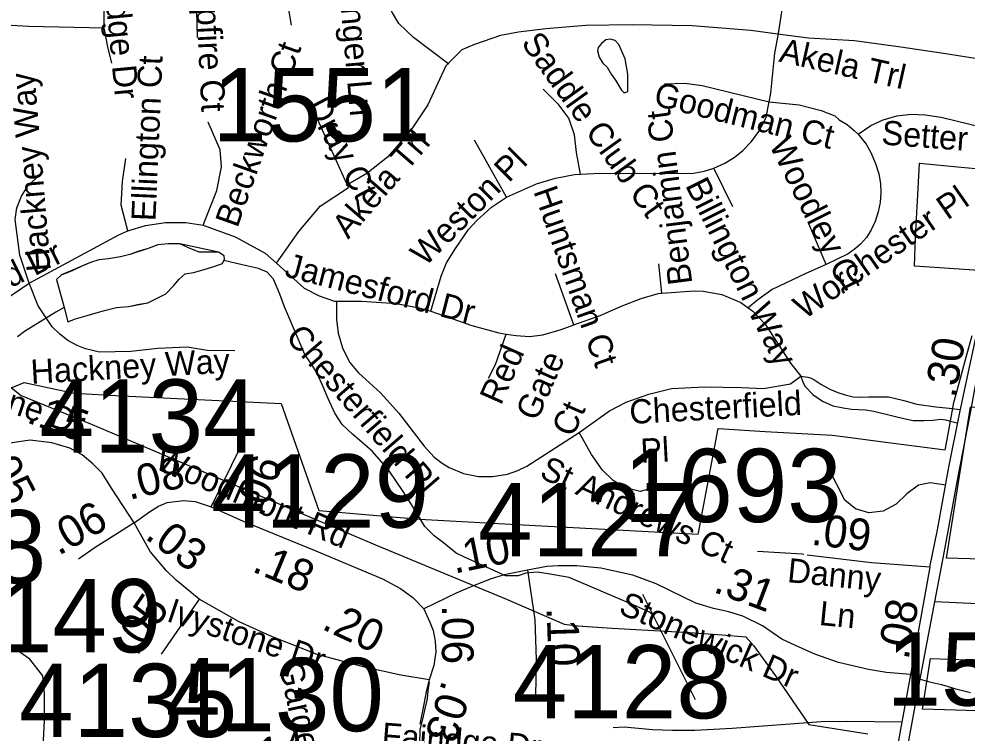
# Model space of a CAD drawing. Extents: x 1662474 to 1856135, y 779280 to 917889.
# Drawn here: x 1723616 to 1727342, y 830593 to 833399 of the extents above; entities that cross this region are included whole.
import ezdxf

# ---------------------------------------------------------------- set-up
doc = ezdxf.new("R2010")
doc.units = 0
for name, color, linetype in [('Cogo Default Point CELL', 7, 'Continuous'), ('Exist Boundary Political City Limit New', 7, 'Continuous'), ('Exist Hydrographic Misc Water Feature', 7, 'Continuous'), ('Exist Hydrographic Pond Under 1500 Sq Ft', 7, 'Continuous'), ('Exist Road Non-System Type 51', 7, 'Continuous'), ('Exist Road Non-System Type 51 Label', 7, 'Continuous'), ('Exist Road Secondary Mileage Tenths English Label', 7, 'Continuous'), ('Exist Road Secondary Type 51 Attributed', 7, 'Continuous'), ('Exist Road Secondary Type 51 Divided Attributed', 7, 'Continuous'), ('Exist Road Secondary Type 51 Label', 7, 'Continuous'), ('Exist Utilities Electrical Transmission Line', 7, 'Continuous'), ('Map Preparation Boundary City Limit Buffer Line', 7, 'Continuous')]:
    doc.layers.add(name, color=color, linetype=linetype)

msp = doc.modelspace()

# ---------------------------------------------------------------- linework, layer by layer
at = {"layer": 'Exist Boundary Political City Limit New'}
for points in [[(1727389.6, 832410), (1727135.1, 832427.2), (1727140.2, 832541.9), (1727148.4, 832707), (1727154.9, 832832.4), (1727156.5, 832832.2), (1727276.9, 832820.2), (1727431.2, 832805.6)], [(1725190.4, 831433.2), (1725573.1, 831412.8), (1726285.4, 831373.6), (1726286.4, 831378.9), (1726364.4, 831789), (1726365.4, 831788.9), (1726549.1, 831778.2), (1726812.6, 831763.2), (1726854.1, 831757.9), (1727012.6, 831737.3), (1727256.6, 831705.6), (1727257.6, 831711.1), (1727269.5, 831775.4), (1727290.5, 831891), (1727299.9, 831924.6), (1727339.2, 832069.2), (1727362.8, 832154.9)], [(1723288, 831825.6), (1723636.5, 831970.3), (1723833.2, 831927.6), (1724020.8, 831917.3), (1724646, 831887.5), (1724794.4, 831467.4), (1724795.4, 831467.4), (1724870, 831460.9), (1725190.4, 831433.2)], [(1729142.6, 831829.8), (1729118.1, 831226.9), (1727260.9, 831280.2), (1727355.8, 831874.2), (1729142.6, 831829.8)], [(1729103.2, 830822.3), (1729099, 830629.8), (1728968.8, 830633.4), (1728118.2, 830657.7), (1727167, 830686.4), (1727177.1, 830753.4), (1727199.1, 830885.4), (1727347.4, 830880.3), (1727479.9, 830875.7), (1727771.5, 830865.6), (1728174.1, 830851.8), (1728462.2, 830842.8), (1728946.4, 830827.4), (1729103.2, 830822.3)]]:
    msp.add_lwpolyline(points, dxfattribs=at)
at = {"layer": 'Exist Hydrographic Misc Water Feature'}
for points in [[(1724421.6, 832449.4), (1724424, 832454.3), (1724422, 832468.3), (1724400.1, 832481.9), (1724366.2, 832482.5), (1724324.2, 832482.5), (1724282.1, 832499.1), (1724248.1, 832514.5), (1724202.2, 832514.6), (1724162, 832511.3), (1724124.1, 832497.3), (1724087.8, 832485.7), (1724051.7, 832473.4), (1724015.6, 832463.4), (1723967.4, 832456.2), (1723929.7, 832452), (1723897.5, 832442), (1723865.3, 832428), (1723827.3, 832410.6), (1723799, 832398.1), (1723783.1, 832392.7), (1723763.6, 832375), (1723793.5, 832264.4)], [(1724421.6, 832449.4), (1724424, 832454.3), (1724422, 832468.3), (1724400.1, 832481.9), (1724248.1, 832514.5), (1724202.2, 832514.6), (1724162, 832511.3), (1724124.1, 832497.3), (1724051.7, 832473.4), (1724015.6, 832463.4), (1723967.4, 832456.2), (1723929.7, 832452), (1723897.5, 832442), (1723783.1, 832392.7), (1723763.6, 832375), (1723793.5, 832264.4)], [(1723793.5, 832264.4), (1723808.5, 832208.3), (1723838.2, 832220), (1723884.6, 832233.9), (1723946.7, 832251.5), (1723999, 832265.2), (1724047, 832269.1), (1724089, 832277.3), (1724123.2, 832283.2), (1724159.1, 832301.3), (1724193.2, 832318.7), (1724225.3, 832350.9), (1724245.4, 832376.7), (1724269.6, 832396.7), (1724301.8, 832402.6), (1724343.9, 832414.1), (1724381.8, 832426.4), (1724415.8, 832438), (1724421.6, 832449.4)], [(1723793.5, 832264.4), (1723808.5, 832208.3), (1723838.2, 832220), (1723884.6, 832233.9), (1723946.7, 832251.5), (1723999, 832265.2), (1724047, 832269.1), (1724123.2, 832283.2), (1724159.1, 832301.3), (1724193.2, 832318.7), (1724225.3, 832350.9), (1724245.4, 832376.7), (1724269.6, 832396.7), (1724301.8, 832402.6), (1724343.9, 832414.1), (1724381.8, 832426.4), (1724415.8, 832438), (1724421.6, 832449.4)], [(1725126.1, 831542.3), (1725071.2, 831623), (1725041.5, 831658.9), (1725005.4, 831699), (1724963.7, 831735.1), (1724927.7, 831765.4), (1724885.8, 831805.7), (1724857.9, 831849.7), (1724830.3, 831910.1), (1724808.3, 831962.3), (1724786.6, 832008.7), (1724770.6, 832034.5), (1724739, 832080.2), (1724659.4, 832267.3), (1724641.8, 832316.9), (1724616.2, 832375.7), (1724592, 832403.3), (1724558.1, 832417.9), (1724510, 832428), (1724421.6, 832449.4)], [(1723793.5, 832264.4), (1723760.5, 832246.2), (1723638.1, 832170.8), (1723610, 832149.2)], [(1726112, 831052.8), (1726092.1, 831068.8), (1726030.2, 831097.2), (1725778.2, 831204), (1725696.4, 831218), (1725652.3, 831224.7), (1725608, 831220.6), (1725577.9, 831210.6), (1725528, 831210.8), (1725364.2, 831285.5), (1725334.3, 831300), (1725284.2, 831339.6), (1725248.4, 831368.3), (1725210.6, 831404.3), (1725182.7, 831452.5), (1725156.7, 831494.9), (1725126.1, 831542.3)]]:
    msp.add_lwpolyline(points, dxfattribs=at)
at = {"layer": 'Exist Hydrographic Pond Under 1500 Sq Ft'}
msp.add_lwpolyline([(1726008.5, 833115.2), (1726008.5, 833182.1), (1725998.2, 833242.2), (1725974.2, 833298.8), (1725958.7, 833314.3), (1725939.8, 833319.4), (1725922.7, 833316), (1725905.5, 833302.3), (1725891.8, 833286.8), (1725890, 833273.1), (1725896.9, 833249.1), (1725910.7, 833225), (1725927.8, 833209.6), (1725943.3, 833182.1), (1725960.4, 833158.1), (1725975.9, 833132.4), (1725984.5, 833118.6), (1725994.8, 833108.3), (1726006.8, 833111.8), (1726008.5, 833115.2)], dxfattribs=at)
at = {"layer": 'Exist Road Non-System Type 51'}
for p, q in [((1724317.9, 833325.6), (1724308.6, 833723.8)), ((1724911, 832735.9), (1724783.2, 833019.5)), ((1725532, 832698.5), (1725406, 832921.9)), ((1726421.2, 832660.2), (1726347, 832812.2)), ((1726788.4, 832433.2), (1726720.4, 832593.6)), ((1726143, 832321.1), (1726131, 832436.4)), ((1725796.6, 832196.4), (1725724.9, 832397))]:
    msp.add_line(p, q, dxfattribs=at)
for points in [[(1724686.6, 833373.6), (1724662.2, 833523.4), (1724658.9, 833585.9), (1724667.4, 833756.2)], [(1725305.2, 833220.6), (1725166.6, 833325.6), (1725109.5, 833380.7), (1725084, 833422.7), (1725054.2, 833482.2), (1725034.4, 833525.6), (1725017.6, 833599.9), (1725012.6, 833666.5), (1725016.6, 833724.5)], [(1723951.2, 833363.9), (1723951.2, 833406.9), (1723953.4, 833525.6), (1723960.6, 833682)], [(1726599.4, 833333.7), (1726623.6, 833487.2), (1726635.4, 833529.8)], [(1723540.8, 833377), (1723654, 833370.7), (1723951.2, 833363.9)], [(1723981.4, 833224.8), (1723965.9, 833289.4), (1723951.2, 833363.9)], [(1726564.6, 833073.4), (1726571.6, 833107.4), (1726587.1, 833263.9), (1726599.4, 833333.7)], [(1726153, 833143.4), (1726233.6, 833146), (1726301.4, 833137.1), (1726564.6, 833073.4)], [(1725823.1, 832788.9), (1725807.4, 832873.6), (1725798.9, 832943.7), (1725776.9, 833009), (1725737.9, 833061), (1725676.1, 833122.9)], [(1726347, 832812.2), (1726390, 832831.6), (1726426.8, 832854.2), (1726460.4, 832881.2), (1726494.8, 832916.9), (1726523.9, 832956.5), (1726547, 833000.4), (1726552.5, 833013.2), (1726564.6, 833073.4)], [(1726564.6, 833073.4), (1726682.4, 833061), (1726768.8, 833039.2), (1726822.9, 833017.4), (1726839.9, 833002.8), (1726870.6, 832983.6), (1726898.8, 832960.7), (1726914.6, 832945.8)], [(1726914.6, 832945.8), (1726964.5, 832980.1), (1727012.6, 833001.9), (1727065.6, 833017.4), (1727122.6, 833024.5), (1727178.1, 833021.4), (1727240.6, 833012.2), (1727406.2, 832971.8)], [(1724339.9, 832588.4), (1724394, 832725.2), (1724412.4, 832818.2), (1724407.4, 832884.9), (1724359.4, 832993.4)], [(1726914.6, 832945.8), (1726945.4, 832906.2), (1726963.5, 832874.1), (1726982.6, 832830.9), (1726995, 832789.4), (1727001.6, 832752.4), (1727003, 832714.9), (1727000.2, 832677.2), (1726992.6, 832640.5), (1726981.1, 832602.2), (1726965.9, 832570.2), (1726946.6, 832540.5), (1726923.4, 832513.8), (1726903.6, 832496.2), (1726874.8, 832476), (1726788.4, 832433.2)], [(1724043.9, 832566), (1724017.4, 832667), (1724022.4, 832760.2), (1724036, 832850.2)], [(1723655.9, 832359.9), (1723618.9, 832470.4), (1723600.6, 832610.4), (1723607.6, 832657.1), (1723626, 832701.9), (1723652.5, 832743.7), (1723711.6, 832797.8)], [(1725823.1, 832788.9), (1725875.4, 832791.4), (1726266.9, 832792.5), (1726309.4, 832800.1), (1726347, 832812.2)], [(1725532, 832698.5), (1725649.6, 832750.2), (1725724.6, 832773.4), (1725800, 832787.5), (1725823.1, 832788.9)], [(1724627.9, 832438.7), (1724715.5, 832563.7), (1724800.2, 832662.6), (1724911, 832735.9)], [(1725235.1, 832250), (1725275.9, 832388.6), (1725296.1, 832440.9), (1725331.2, 832496.2), (1725382.9, 832571.2), (1725415.8, 832606.4), (1725472.6, 832659.2), (1725532, 832698.5)], [(1724043.9, 832566), (1724113.4, 832587.5), (1724192.4, 832599.4), (1724272.5, 832599.4), (1724339.9, 832588.4)], [(1724339.9, 832588.4), (1724465.6, 832542.4), (1724584, 832478.9), (1724627.9, 832438.7)], [(1723655.9, 832359.9), (1724008.6, 832550.5), (1724043.9, 832566)], [(1724627.9, 832438.7), (1724737.2, 832340.5), (1724795.9, 832311.2), (1724855.6, 832289.9), (1724863.5, 832289.9)], [(1726788.4, 832433.2), (1726708.4, 832398.2), (1726575.9, 832335), (1726519.4, 832295.4), (1726482.4, 832263.4)], [(1723557.8, 832293.9), (1723655.9, 832359.9)], [(1724464.4, 832094.1), (1724355.9, 832095.4), (1724277.1, 832109), (1724162.2, 832103.9), (1724055.8, 832092.5), (1723932.4, 832088.9), (1723877.1, 832101.9), (1723844.4, 832115.4), (1723808.4, 832134.8), (1723776.1, 832160), (1723747.2, 832189.1), (1723691.1, 832272), (1723655.9, 832359.9)], [(1725796.6, 832196.4), (1725900.2, 832233.8), (1725986.6, 832272), (1726060.9, 832299.9), (1726128.4, 832319.9), (1726143, 832321.1)], [(1726143, 832321.1), (1726269.2, 832330.6), (1726304.8, 832328.8), (1726378.1, 832315.4), (1726453.5, 832284.9), (1726482.4, 832263.4)], [(1724863.5, 832289.9), (1724963.2, 832290.2), (1725098.1, 832281.2), (1725188.5, 832263.9), (1725235.1, 832250)], [(1724863.5, 832289.9), (1724863.5, 832217.7), (1724870.9, 832163.4), (1724887.1, 832106.4), (1724915.2, 832049.8), (1724950.4, 832008.5), (1725037.6, 831930.1), (1725108.4, 831849.2), (1725208.1, 831720.1), (1725248.4, 831676.2), (1725279, 831652.9), (1725307.1, 831635.9), (1725362.8, 831612.8), (1725421.8, 831600.9), (1725476.6, 831600.2), (1725535.6, 831610.1), (1725577.1, 831624.2), (1725611.6, 831641.4), (1725817.9, 831773.4)], [(1725235.1, 832250), (1725395.6, 832194.4), (1725502.6, 832164.9), (1725530.8, 832160.5)], [(1726482.4, 832263.4), (1726500.8, 832249.8), (1726549.4, 832198.9), (1726648.2, 832046.1), (1726689.5, 831994.6)], [(1725530.8, 832160.5), (1725570.1, 832154.4), (1725622.4, 832151), (1725674.9, 832156.9), (1725746.8, 832177.9), (1725796.6, 832196.4)], [(1725461.1, 831987.2), (1725488.4, 832040.5), (1725530.8, 832160.5)], [(1725817.9, 831773.4), (1725937.5, 831859), (1726002.9, 831892.5), (1726091.6, 831923.8), (1726180.4, 831946.1), (1726310.5, 831952.6), (1726456.1, 831949.9), (1726542.8, 831946.9), (1726648.5, 831964.9), (1726689.5, 831994.6)], [(1726689.5, 831994.6), (1726716.9, 831991.6), (1726730.1, 831987.5), (1726740.1, 831981.7), (1726767.5, 831963.4), (1726802.4, 831944.4), (1726833.9, 831931.1), (1726863.8, 831921.1), (1726894.5, 831914.4), (1726920.1, 831912.8), (1726956.6, 831913.6), (1727001.5, 831914.4), (1727033, 831913.6), (1727055.4, 831908.7), (1727093.6, 831899.5), (1727144.2, 831885.4), (1727218.9, 831874.6), (1727272, 831869.7), (1727313.4, 831863.9)], [(1726689.5, 831994.6), (1726698.6, 831969.2), (1726706.1, 831954.2), (1726736, 831922.8), (1726774.1, 831896.2), (1726814.9, 831878.8), (1726855.5, 831870.5), (1726887.9, 831865.5), (1726943.4, 831862.2), (1726975.8, 831857.2), (1727055.4, 831838.1), (1727093.6, 831828.2), (1727131, 831820.7), (1727174.1, 831820.7), (1727207.4, 831822.4), (1727238.9, 831825.7), (1727257.1, 831824), (1727277, 831818.2), (1727303.8, 831811.5)], [(1726114.6, 831557.1), (1726058, 831542.1), (1725995.5, 831557.1), (1725951.4, 831585.4), (1725909.6, 831625.1), (1725865.9, 831687.5), (1725817.9, 831773.4)], [(1727258.6, 831567.2), (1727197.4, 831576), (1727150.9, 831566.2), (1727105.5, 831532.2), (1727063.5, 831492.6), (1727012.4, 831464.2), (1726956.6, 831457.9), (1726904.1, 831473.6), (1726862.1, 831507.2), (1726796, 831636.1)], [(1726700.8, 831294.7), (1726694.1, 831295.4), (1726519.1, 831305.6)], [(1728613.6, 831018.8), (1728560.4, 831035.4), (1728497.4, 831043.7), (1727986.1, 831075.2), (1727746.1, 831081.2), (1727578.2, 831091.8), (1727215, 831108.9)], [(1725189.2, 830445.9), (1725192.9, 830605.9), (1725206.1, 830658.7), (1725211.9, 830689.7), (1725221.5, 830726.7), (1725224.9, 830760), (1725229.9, 830793.1)], [(1727157.5, 830804.2), (1727194.1, 830793.9), (1727241.8, 830782.9), (1727298.4, 830766.9), (1727355.9, 830752)], [(1727084.2, 830635.9), (1726871.9, 830638.5), (1726769, 830636.9), (1726419.1, 830610.1), (1726272.1, 830603.4), (1726184.2, 830602.5), (1726106.2, 830605.9), (1725994.6, 830615.4), (1725951.5, 830613.8)]]:
    msp.add_lwpolyline(points, dxfattribs=at)
at = {"layer": 'Exist Road Secondary Type 51 Attributed'}
for p, q in [((1724371.6, 831482.1), (1724492.6, 831725.9)), ((1724324.5, 831118.4), (1724175.4, 830902.1))]:
    msp.add_line(p, q, dxfattribs=at)
for points in [[(1727747.9, 833132.3), (1727571.9, 833198.6), (1727448.6, 833231.5), (1727249.3, 833262.4), (1727081.8, 833287.8), (1726899.2, 833312.1), (1726719.7, 833323), (1726607.8, 833337.8), (1726491.8, 833353.1), (1726261.7, 833371.2), (1726025.6, 833375.2), (1725843.5, 833372.7), (1725687.2, 833360), (1725579, 833347), (1725508.7, 833333.7), (1725406.4, 833298.5), (1725356.4, 833277.1), (1725293.2, 833213.9), (1725222.4, 833061), (1725162.2, 832970.2), (1725101.9, 832898.4), (1725064.2, 832855.4), (1724983.6, 832791.7), (1724902.2, 832744.7)], [(1724069, 831418.9), (1723980, 831555.1), (1723943.3, 831614.4), (1723906.6, 831651), (1723864.7, 831685.9), (1723815.8, 831712.1), (1723745.9, 831733.1), (1723659.6, 831743.8), (1723580.6, 831732.4), (1723496.5, 831706.9), (1723437.7, 831683.3)], [(1723711.2, 830539.7), (1723717.1, 830640.9), (1723717.1, 830748.2), (1723710.1, 830817.5), (1723658.2, 830883.3), (1723588.9, 830931.8), (1723478, 830959.5), (1723381, 830973.3), (1723214.7, 830976.8), (1723110.7, 831004.5), (1723048.4, 831070.3), (1723006.8, 831163.8), (1723010.3, 831253.8), (1723041.4, 831347.3), (1723114.2, 831506.6)], [(1724069, 831418.9), (1724128.7, 831462.2), (1724163.9, 831483.9), (1724198.7, 831498.8), (1724262.6, 831506.9), (1724308.9, 831502), (1724371.6, 831482.1)], [(1724371.6, 831482.1), (1724496.8, 831425.6), (1724776.8, 831311.2), (1725044.6, 831199), (1725115.3, 831161), (1725164.4, 831124.8), (1725206.7, 831081.2)], [(1724069, 831418.9), (1723997.4, 831373.5), (1723915.3, 831321.2), (1723850.7, 831275.8)], [(1724324.5, 831118.4), (1724233.8, 831193.8), (1724196.2, 831230.2), (1724131.9, 831306), (1724069, 831418.9)], [(1727196.2, 831245), (1726966.2, 831261.3), (1726713.5, 831291.7)], [(1725614.2, 831232.4), (1725523.1, 831215), (1725472.1, 831198.4), (1725404.9, 831172.9), (1725334.7, 831142.8), (1725206.7, 831081.2)], [(1727120.2, 830822.9), (1727026, 830831.1), (1726954.6, 830842.8), (1726837.6, 830869.6), (1726744.4, 830902.1), (1726667.7, 830936.8), (1726614.5, 830962.2), (1726537.8, 831013.4), (1726461.1, 831051.8), (1726405.7, 831068.8), (1726345.2, 831082.3), (1726275.8, 831103.6), (1726120.3, 831179.5), (1726028.7, 831213.5), (1725903, 831240.9), (1725809.2, 831250.3), (1725735.2, 831250.3), (1725690.4, 831247.2), (1725614.2, 831232.4)], [(1725614.2, 831232.4), (1725643.2, 831037.6), (1725648.2, 830882.1), (1725645.7, 830736.6)], [(1725227.8, 830801.8), (1725116.4, 830820.2), (1724973.8, 830851.1), (1724788.7, 830900.9), (1724605.6, 830974), (1724481, 831030.4), (1724324.5, 831118.4)], [(1725206.7, 831081.2), (1725231, 831027.9), (1725244, 830996.1), (1725251.3, 830954.2), (1725254.2, 830912.3), (1725246.9, 830858.8), (1725227.8, 830801.8)], [(1727159.8, 830819.5), (1727120.2, 830822.9)], [(1725227.8, 830801.8), (1725217.8, 830761.7), (1725207.8, 830706.5), (1725191.9, 830627.7)]]:
    msp.add_lwpolyline(points, dxfattribs=at)
at = {"layer": 'Exist Road Secondary Type 51 Divided Attributed'}
msp.add_line((1727196.2, 831245), (1727120.2, 830822.9), dxfattribs=at)
for points in [[(1727196.2, 831245), (1727225.7, 831391.8), (1727271, 831637.5), (1727313.5, 831851.7), (1727340.3, 831975.2), (1727399.3, 832249.7), (1727414.4, 832306), (1727459.7, 832436.4), (1727562.6, 832694.4), (1727747.9, 833132.3)], [(1727622.3, 832737), (1727601.7, 832677.9), (1727542.7, 832535.2), (1727485.1, 832392.4), (1727448, 832285.4), (1727432.9, 832230.5), (1727391.1, 832052), (1727352.6, 831843.4), (1727305.3, 831600.5), (1727255.2, 831321.8), (1727159.8, 830819.5)], [(1727120.2, 830822.9), (1727041.1, 830391.2), (1727004.7, 830207.3), (1726980, 830097.5), (1726956.6, 830026.1), (1726889.4, 829807.9), (1726816, 829600.6), (1726752.1, 829400.3), (1726654.7, 829099.7), (1726582.6, 828888.3), (1726545.6, 828789.5), (1726511.2, 828718.1)], [(1727159.8, 830819.5), (1727063, 830300.7), (1727040.4, 830193.6), (1727015.7, 830092), (1727000.6, 830023.4), (1726927.8, 829812), (1726872.2, 829635)]]:
    msp.add_lwpolyline(points, dxfattribs=at)
at = {"layer": 'Exist Road Secondary Type 51 Label'}
msp.add_lwpolyline([(1726274.5, 830723.2), (1726067.6, 831137)], dxfattribs=at)
msp.add_lwpolyline([(1726274.5, 830723.2), (1726067.6, 831137)], dxfattribs=at)
at = {"layer": 'Exist Utilities Electrical Transmission Line'}
msp.add_lwpolyline([(1723561.3, 831968.3), (1723624.9, 831919.6), (1723903.9, 831804.7), (1725017.8, 831332.8), (1725532.2, 831119.2), (1725759.2, 831020.7), (1725813.1, 831014.2), (1725947.1, 831004.9), (1726251.3, 830987.7), (1726379.2, 830978.3), (1726473.3, 830971.4), (1726503, 830936.9), (1726589.9, 830818.1), (1726719.8, 830626.6), (1726951.6, 830590.2)], dxfattribs=at)
at = {"layer": 'Map Preparation Boundary City Limit Buffer Line'}
for points in [[(1727389.6, 832410), (1727135.1, 832427.2), (1727140.2, 832541.9), (1727148.4, 832707), (1727154.9, 832832.4), (1727156.5, 832832.2), (1727276.9, 832820.2), (1727431.2, 832805.6)], [(1725190.4, 831433.2), (1725573.1, 831412.8), (1726285.4, 831373.6), (1726286.4, 831378.9), (1726364.4, 831789), (1726365.4, 831788.9), (1726549.1, 831778.2), (1726812.6, 831763.2), (1726854.1, 831757.9), (1727012.6, 831737.3), (1727256.6, 831705.6), (1727257.6, 831711.1), (1727269.5, 831775.4), (1727290.5, 831891), (1727299.9, 831924.6), (1727339.2, 832069.2), (1727362.8, 832154.9)], [(1723288, 831825.6), (1723636.5, 831970.3), (1723833.2, 831927.6), (1724020.8, 831917.3), (1724646, 831887.5), (1724794.4, 831467.4), (1724795.4, 831467.4), (1724870, 831460.9), (1725190.4, 831433.2)], [(1729142.6, 831829.8), (1729118.1, 831226.9), (1727260.9, 831280.2), (1727355.8, 831874.2), (1729142.6, 831829.8)], [(1729103.2, 830822.3), (1729099, 830629.8), (1728968.8, 830633.4), (1728118.2, 830657.7), (1727167, 830686.4), (1727177.1, 830753.4), (1727199.1, 830885.4), (1727347.4, 830880.3), (1727479.9, 830875.7), (1727771.5, 830865.6), (1728174.1, 830851.8), (1728462.2, 830842.8), (1728946.4, 830827.4), (1729103.2, 830822.3)]]:
    msp.add_lwpolyline(points, dxfattribs=at)

# ---------------------------------------------------------------- texts
at = {"layer": 'Cogo Default Point CELL'}
for s, p in [('1551', (1724376.4, 832917.3)), ('4134', (1723697.1, 831694.4)), ('4129', (1724371.3, 831399.8)), ('1693', (1725992.9, 831421.7)), ('4127', (1725420.1, 831286.8)), ('4148', (1722866.1, 831181)), ('4149', (1723319.2, 830909.8)), ('1546', (1727025.7, 830700.6)), ('4128', (1725557, 830650.3)), ('4135', (1723617, 830577.2)), ('4130', (1724193.5, 830600))]:
    msp.add_text(s, height=288, dxfattribs=at).set_placement(p)
at = {"layer": 'Exist Road Non-System Type 51 Label'}
for s, rotation, p in [('Camp Ranger Ln', 274.9668, (1724834.5, 833977.3)), ('Campfire Ct', 272.8607, (1724299.7, 833708.8)), ('Lodge Dr', 275.482, (1723944.5, 833600.6)), ('Saddle Club Ct', 305.7378, (1725587.1, 833304)), ('Beckworth Ct', 70.4741, (1724474.6, 832574.4)), ('Ellington Ct', 87.5119, (1724152.5, 832602.8)), ('Hackney Way', 94.7608, (1723741.7, 832409.9)), ('Goodman Ct', 346.0796, (1726106.2, 833060.5)), ('Dray Ct', 297.8101, (1724743.8, 833060.2)), ('Benjamin Ct', 97.2899, (1726262.8, 832359.5)), ('Setter Ct', 355.624, (1727003.9, 832905.7)), ('Woodley Ct', 296.5514, (1726562.1, 832905)), ('Weston Pl', 45.1042, (1725212.3, 832422.3)), ('Billington Way', 296.5514, (1726233.1, 832744.8)), ('Huntsman Ct', 289.4294, (1725637, 832721.7)), ('Worchester Pl', 34.7938, (1726702.8, 832215.4)), ('Jamesford Dr', 26.6633, (1723115.7, 832105.3)), ('Jamesford Dr', 345.6104, (1724655.7, 832387.9)), ('Chesterfield Pl', 310.8175, (1724660.3, 832146.8)), ('Hackney Way', 3.2674, (1723664.7, 831964.8)), ('Red', 66.0501, (1725510.1, 831877.2)), ('Gate', 66.0501, (1725651.8, 831814.3)), ('Chesterfield', 3.0776, (1726017.7, 831807.1)), ('Ct', 66.0501, (1725793.4, 831751.4)), (' Pl', 3.0776, (1726026, 831652.3)), ('St Andrews Ct', 335.2119, (1725657.3, 831598.5))]:
    msp.add_text(s, height=95, rotation=rotation, dxfattribs=at).set_placement(p)
at = {"layer": 'Exist Road Secondary Mileage Tenths English Label'}
for s, rotation, p in [('.30', 80.6465, (1727297.4, 831905.9)), ('.15', 339.8745, (1723641.4, 831814.8)), ('.05', 297.5211, (1723469.7, 831684.9)), ('.06', 69.3045, (1724572.6, 831436)), ('.08', 13.2348, (1724049.5, 831508.4)), ('.06', 29.2774, (1723771.2, 831288)), ('.09', 353.1469, (1726726.6, 831333.3)), ('.03', 323.3657, (1724106.9, 831359.8)), ('.10', 11.4528, (1725327.3, 831218.8)), ('.18', 337.4852, (1724527.7, 831229.1)), ('.31', 339.1563, (1726340.7, 831148.7)), ('.05', 55.4456, (1724079.3, 830891.1)), ('.20', 334.7991, (1724801.8, 831003.5)), ('.08', 79.7407, (1727111.6, 830877.7)), ('.06', 270, (1725278.1, 831095.9)), ('.10', 271.8486, (1725689.7, 831084.7)), ('.03', 252.4449, (1725280.8, 830804.1)), ('.14', 10.3004, (1724525.1, 830438.2))]:
    msp.add_text(s, height=125, rotation=rotation, dxfattribs=at).set_placement(p)
at = {"layer": 'Exist Road Secondary Type 51 Label'}
for s, rotation, p in [('Akela Trl', 347.3568, (1726599.5, 833231.8)), ('Akela Trl', 49.1792, (1724909.9, 832530.7)), ('Ivystone Dr', 341.5546, (1723247.5, 831961.1)), ('Woodmont Rd', 336.8731, (1724144.2, 831634.4)), ('Danny', 354.237, (1726633.2, 831186.2)), ('Ivystone Dr', 341.5546, (1724191.7, 831034.2)), ('Stonewick Dr', 336.4419, (1725967.8, 831064.9)), (' Ln', 354.237, (1726722.9, 831021.4)), ('Gardenwood Pl', 282.2292, (1724635.9, 830864.1)), ('Fairidge Dr', 355.4635, (1725039.1, 830539.8))]:
    msp.add_text(s, height=95, rotation=rotation, dxfattribs=at).set_placement(p)

doc.saveas('drawing.dxf')
